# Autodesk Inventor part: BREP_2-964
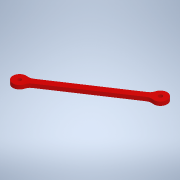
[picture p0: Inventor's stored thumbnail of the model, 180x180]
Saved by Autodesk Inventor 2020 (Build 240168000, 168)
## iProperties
Created: 2017-09
Part Number: BREP_2-964
Material: Générique
Document SubType Name: Modeling
Designer: bruno
Density: 1 g/cm^3
Appearance: Rouge
Mass: 7.10262 g
Surface Area: 46.691 cm^2
Volume: 7.10262 cm^3
Sending System: SolidWorks 2016
Author: bruno
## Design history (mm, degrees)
feature "Importée1"
node "Solide1"
